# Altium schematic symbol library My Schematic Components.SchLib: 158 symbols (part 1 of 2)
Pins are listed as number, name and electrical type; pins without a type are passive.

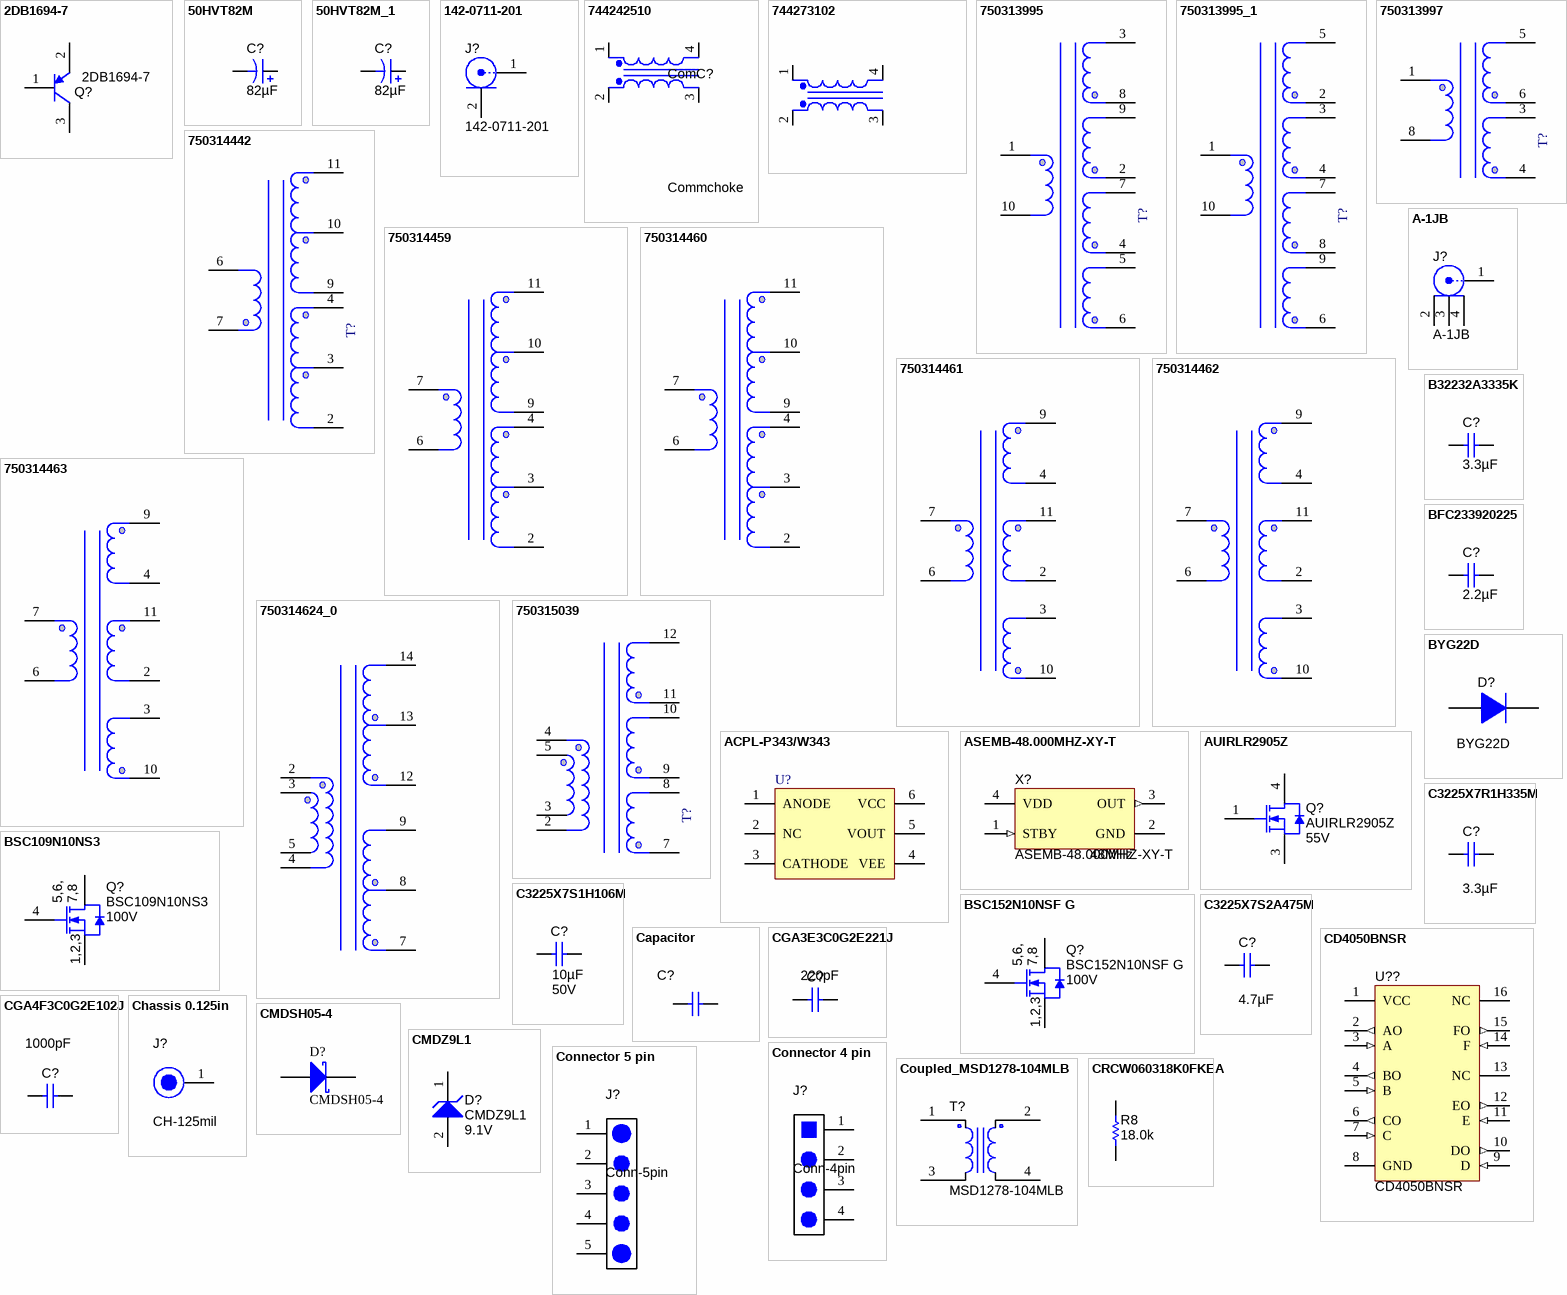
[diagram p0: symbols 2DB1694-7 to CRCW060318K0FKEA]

## 2DB1694-7
designator Q?
TRANS BIPO PNP 30V 1A SOT-323; Manufacturer: Diodes Inc.; CompType: BJT; U/M: EA; PNP: 1; NPN: 0; Vceo_V: 30; Vcesat1_V: 0.380; Value: 0.38V; HfeMax: 680; Value2: 600
simulation model DI_BC858C
footprint SOT-323 DIODES INC
pins: 1 B, 2 E, 3 C

## 50HVT82M
designator C?  ValueDisplayed: 82µF  (hidden comment: 50HVT82M)
CAP, AL EP, 82uF, 50V, +/-20%, 0.019 ohm, SMD; Manufacturer: Suncon; Cap_Case: 10x12.5; ESR_Ohm: 0.019; IRMS_A: 1.27; Polarized: Y; TaMax_C: 135; TaMin_C: -55; Tolerance_%: 20; VDC_V: 50; CompType: Capacitor; Cap_F: 82.0E-6; U/M: EA
signal-integrity model Cap
simulation model Cap
footprint SM_RADIAL_10x12.5mm (Suncon 10x12.5)
pins: 1 +, 2 -

## 50HVT82M_1
designator C?, comment ValueDisplayed: 82µF  (hidden comment: 50HVT82M)
CAP, AL EP, 82uF, 50V, +/-20%, 0.019 ohm, SMD; Manufacturer: Suncon; Cap_Case: 10x12.5; ESR_Ohm: 0.019; IRMS_A: 1.27; Polarized: Y; TaMax_C: 135; TaMin_C: -55; Tolerance_%: 20; VDC_V: 50; CompType: Capacitor; Cap_F: 82.0E-6; U/M: EA
signal-integrity model Cap
simulation model Cap
footprint SM_RADIAL_10x12.5mm (Suncon 10x12.5)
pins: 1 +, 2 -

## 142-0711-201
designator J?
Connector, SMA Jack, Vertical, Gold, SMD; Manufacturer: Emerson Network Power; SymbolCreator: codlsc; U/M: EA
signal-integrity model SI Model (SI Default Model)
footprint 142-0711-201
pins: 1, 2

## 744242510
designator ComC?, comment Commchoke
CHOKE COMM MODE 51uH 2.5kOHM .4A SMD; Manufacturer: Wurth Electronics Inc; PartNumber: 744242510; Filter Type: Data, Signal Line; Number of Lines: 2; ValueDisplayed: 51µH; Irms: 400mA; DCR_Ohm: 320 mOhm Max
footprint WE-SLM Choke (WE-SLM SMD Common Mode Choke)
pins: 1 Sec+, 2 Pri+, 3 Pri-, 4 Sec-

## 744273102
designator L?
Wurth 744273102 2A Common Mode Choke; Manufacturer: Wurth Elektronik; SymbolVersion: use current date i.e. 2008-05-20; SymbolCreator: Use a-id; CompType: Used in some BOM reports.  Useful for finding later.; U/M: EA, IN, or GM
pins: 1 Sec+, 2 Pri+, 3 Pri-, 4 Sec-

## 750313995
designator T?  (value not drawn)
XFMR, SMT 50uH, 3:2:4, 3:2:4; Manufacturer: Wurth; Area: 240 sq. mm
footprint XFMR_Wurth_EP13_10pin_SMT (Recommended land pattern for Pulse Engineering PA3856.006NL transformer)
pins: 1, 2, 3, 4, 5, 6, 7, 8, 9, 10

## 750313995_1
designator T?, comment 750313995  (value not drawn)
XFMR, SMT 50uH, 3:2:4, 3:2:4; Manufacturer: Wurth; Area: 240 sq. mm
footprint XFMR_Wurth_EP13_10pin_SMT (Recommended land pattern for Pulse Engineering PA3856.006NL transformer)
footprint XFMR_Wurth_EP13_EP10_Comb_SMT (Recommended land pattern for Wurth EP13 package (10pin) transformer)
pins: 1, 2, 3, 4, 5, 6, 7, 8, 9, 10

## 750313997
designator T?  (value not drawn)
XFMR, SMT 50uH, 1:1.5:1.5, EP10; Manufacturer: Wurth; Area: 203 sq. mm
footprint XFMR_WURTH_EP10_8PIN_SMT (Recommended land pattern for Wurth EP10 8 pin transformer)
pins: 1, 3, 4, 5, 6, 8

## 750314442
designator T?, comment 750313995  (value not drawn)
XFMR, SMT 50uH, 3:2:4, 3:2:4; Manufacturer: Wurth; Area: 165 sq. mm; Value: 45uH
footprint XFMR_Wurth_ER11p5_12pin_SMT (Recommended land pattern for Wurth ER11p5 - SMT)
pins: 2, 3, 4, 6, 7, 9, 10, 11

## 750314459
designator T?
XFMR, SMT 45uH, 750314459; Manufacturer: Wurth; PCB DECAL: Used in BOM report.  Use Y or N.; Area: 164.465 sq.mm
footprint XFMR_Wurth_ER11p5_12pin_SMT (Recommended land pattern for Wurth ER11p5 - SMT)
pins: 2, 3, 4, 6, 7, 9, 10, 11

## 750314460
designator T?  (value not drawn)
XFMR, SMT 45uH, 750314460; Manufacturer: Wurth; Area: 164.465 sq. mm
footprint XFMR_Wurth_750314460_12pin_SMT (Recommended land pattern for Wurth - SMT)
pins: 2, 3, 4, 6, 7, 9, 10, 11

## 750314461
designator T?
XFMR, SMT 45uH, 750314461; Manufacturer: Wurth Elektronik; PCB DECAL: Used in BOM report.  Use Y or N.; Area: 164.465 sq.mm
footprint Model Name (Footprint not found)
footprint XFMR_Wurth_ER11p5_12pin_SMT (Recommended land pattern for Wurth ER11p5 - SMT)
pins: 2, 3, 4, 6, 7, 9, 10, 11

## 750314462
designator T?
XFMR, SMT 45uH, 750314462; Manufacturer: Wurth Elektronik; PCB DECAL: Used in BOM report.  Use Y or N.; Area: 164.465 sq.mm
footprint XFMR_Wurth_ER11p5_12pin_SMT (Recommended land pattern for Wurth ER11p5 - SMT)
pins: 2, 3, 4, 6, 7, 9, 10, 11

## 750314463
designator T?
XFMR, SMT 45uH, 750314463; Manufacturer: Wurth Elektronik; PCB DECAL: Used in BOM report.  Use Y or N.; Area: 164.465 sq.mm
footprint XFMR_Wurth_ER11p5_12pin_SMT (Recommended land pattern for Wurth ER11p5 - SMT)
pins: 2, 3, 4, 6, 7, 9, 10, 11

## 750314624_0
designator T?
Manufacturer: Wurth
footprint WURTH_750314624_0 (WURTH EF20 through-hole, extended rail)
pins: 2, 3, 4, 5, 7, 8, 9, 12, 13, 14

## 750315039
designator T?  (value not drawn)
Transformer, 45uH, Isat 2.5A, EFD20, 12 pin, SMT, 6:4:11:11; Manufacturer: Wurth Electronics Midcom; Value: 40uH
footprint Wurth_EFD20_12pin_SMT (WURTH EFD20 12pin SMT package)
pins: 2, 3, 4, 5, 7, 8, 9, 10, 11, 12

## A-1JB
designator J?
Connector, RF Jack, Vertical, Gold, SMD; Manufacturer: Amphenol; SymbolCreator: crossc; U/M: EA; Value: 50 ohm
signal-integrity model SI Model (SI Default Model)
footprint A-1JB (Amphenol recommended land pattern)
pins: 1, 2, 3, 4

## ACPL-P343/W343
designator U?
4.0 Amp Output Current IGBT Gate Drive Optocoupler; Manufacturer: Avago Technologies US Inc.; PartNumber: ACPL-W343; Voltage - Isolation: 5000Vrms; Number of Channels: 1, Unidirectional; Current - Output / Channel: 4A; Propagation Delay High - Low @ If: 95ns @ 7mA ~ 16mA; Current - DC Forward (If) (Max): 25mA; Input Type: DC; Output Type: Gate Driver
footprint ACPL-P34x/W34x (AVAGO Stretched SO-6 Package)
pins: 1 ANODE, 2 NC, 3 CATHODE, 4 VEE, 5 VOUT, 6 VCC

## ASEMB-48.000MHZ-XY-T
designator X?  Frequency: 48MHz
Oscillator, 48.000MHz, 1.8-3.3V, SMD; Manufacturer: Abracon Corporation; Function: Standby (Power Down); Output: CMOS; Voltage - Supply: 1.8 V ~ 3.3 V; Frequency Stability: ±10ppm; Current - Supply (Max): 16mA; Current - Supply (Disable) (Max): 15µA
footprint XTAL_ABSEMB3.2_4-SMD (Abracon recommended land pattern)
pins: 1 STBY (in), 2 GND (power), 3 OUT (out), 4 VDD (power)

## AUIRLR2905Z
designator Q?  value 55V
MOSFET, N-CH, 55V, 42A, DPAK; Manufacturer: International Rectifier; Alternate Manufacturer: None; U/M: EA; ChType: N; VdsMax_V: 55; Value1: 0.011 ohm; Rdson: 0.011; Value2: 20 nC; QgTyp_nC: 23; Vgs_V: 16; IdsMax_A: 42
footprint DPAK
pins: 1 G, 3 S, 4 D

## B32232A3335K
designator C?  ValueDisplayed: 3.3µF  (hidden comment: B32232A3335K)
CAP, Film, 3.3uF, 250V, +/-10%, TH; Manufacturer: EPCOS Inc; Polarized: N; TaMax_C: 100; Tolerance_%: 10; VDC_V: 250; Cap_F: 3.3E-6; CompType: Capacitor; Dielectric: B32232; VAC_V: 160; Dielectric Material: Metallized Polyester Film; Maximum Temperature: -40°C ~ 100°C
signal-integrity model Cap
simulation model Cap
footprint CAPPA37-32x14 (Capacitor, Axial; Body 32 x 14 mm (LxDia. max), Lead Dia. 0.8 mm (typ))
pins: 1, 2

## BFC233920225
designator C?, comment ValueDisplayed: 2.2µF  (hidden comment: B32923C3225M)
CAP, Film, 2.2uF, 630V, +/-20%, TH; Manufacturer: EPCOS Inc; Polarized: N; TaMax_C: 110; Tolerance_%: 20; VDC_V: 630; Cap_F: 2.2E-6; CompType: Capacitor; Dielectric: B32923; VAC_V: 310; Dielectric Material: Metallized Polypropylene Film; Lifetime @ Temp.: 1000 Hrs @ 110°C; Maximum Temperature: -55°C ~ 110°C
signal-integrity model Cap
simulation model Cap
footprint MKP_15x25x31.5mm (Flm capacitors, 27.5mm spacing)
pins: 1, 2

## BSC109N10NS3
designator Q?  value 100V
MOSFET, N-CH, 100V, 63A, PG-TDSON-8; Manufacturer: Infineon Technologies; Alternate Manufacturer: None; U/M: EA; ChType: N; VdsMax_V: 100; Value1: 10.9 mohm; Rdson45_Ohm: 0.0125; Value2: 26 nC; QgTyp_nC: 26; Vgs_V: 20; IdsMax_A: 63
footprint PG-TDSON-8
pins: 1 S, 2 S, 3 S, 4 G, 5 D, 6 D, 7 D, 8 D, 9 D

## BSC152N10NSF G
designator Q?  value 100V
MOSFET, N-CH, 100V, 63A, PG-TDSON-8; Manufacturer: Infineon Technologies; Alternate Manufacturer: None; U/M: EA; ChType: N; VdsMax_V: 100; Value1: 101 ohm; Rdson45_Ohm: 101; Value2: 22 nC; QgTyp_nC: 22; Vgs_V: 20; IdsMax_A: 63
footprint PG-TDSON-8
pins: 1 S, 2 S, 3 S, 4 G, 5 D, 6 D, 7 D, 8 D, 9 D

## BYG22D
designator D?
Diode, Ultrafast Avalanche, 200V, 2A, SMA; Manufacturer: Vishay; Vf_V: 1.1; Io_A: 1; Vr_V: 200; TJmax_C: 150; RJC_CperW: 30; Current - Reverse Leakage @ Vr: 1µA @ 200V; Reverse Recovery Time (trr): 25ns; Value: 1.1V
signal-integrity model Diode
footprint SMA - HV (Molded Diode, 2-Leads, Body 4.3x2.6mm. Based on STTH1R06 footprint dimensions and land pattern for 600V.)
pins: 1 K, 2 A

## C3225X7R1H335M
designator C?  ValueDisplayed: 3.3µF  (hidden comment: C3225X7R1H335M)
CAP, CERM, 3.3uF, 50V, +/-20%, X7R, 1210; Manufacturer: TDK; Polarized: N; CompType: Capacitor; U/M: EA; Cap_F: 0.0000033; Tolerance_%: 20; VDC_V: 50; TaMin_C: -55; TaMax_C: 125; Cap_Case: 1210
signal-integrity model Cap
simulation model Cap
footprint 1210
footprint 1210M
footprint 1210L
pins: 1, 2

## C3225X7S1H106M
designator C?  Value2: 50V  ValueDisplayed: 10µF  (hidden comment: C3225X7S1H106M)
CAP, CERM, 10uF, 50V, +/-20%, X7S, 1210; Manufacturer: TDK; Polarized: N; CompType: Capacitor; U/M: EA; Cap_F: 0.000010; Tolerance_%: 20; VDC_V: 50; TaMin_C: -55; TaMax_C: 125; Cap_Case: 1210
signal-integrity model Cap
simulation model Cap
footprint 1210
footprint 1210M
footprint 1210L
pins: 1, 2

## C3225X7S2A475M
designator C?  ValueDisplayed: 4.7µF  (hidden comment: C3225X7S2A475M)
CAP, CERM, 4.7uF, 100V, +/-20%, X7S, 1210; Manufacturer: TDK; Polarized: N; CompType: Capacitor; U/M: EA; Cap_F: 0.0000047; Tolerance_%: 20; VDC_V: 100; TaMin_C: -55; TaMax_C: 125; Cap_Case: 1210
signal-integrity model Cap
simulation model Cap
footprint 1210
footprint 1210M
footprint 1210L
pins: 1, 2

## Capacitor
designator C?, comment Used in BOM report  (value not drawn)
CAP, CERM, xxxF, xxV, [Dielectric], xx%, [Package]; Polarized: N; CompType: Capacitor
simulation model Capacitor
signal-integrity model Cap
footprint TBD (Placeholder for MiscParts)
footprint 0201 (Data from Panasonic ERJ resistor datasheet dated February 2006)
footprint 0402 (0402 from SM-752 data)
footprint 0603 (0603 from SM-752 data)
footprint 0805 (0805 from SM-752 data)
footprint 1206 (1206 from SM-752 data)
footprint 0603_HV (Ernesto recommended land pattern.  26 mil between pads.)
footprint 0805_HV (0805 with 30mil clearance between pads)
footprint 1210 (1210 from SM-752 data)
footprint 1808 (Chip Capacitor, Body 4.6x2.0mm, IPC Medium Density)
footprint 1812
footprint 1825 (Chip Capacitor, Body 4.5x6.4mm, IPC Medium Density)
footprint 2220 (Chip Capacitor, Body 5.7x5.0mm, IPC Medium Density)
footprint 2225 (Chip Capacitor, Body 5.7x6.4mm, IPC Medium Density)
pins: 1, 2
1 alternate drawing of the same symbol

## CD4050BNSR
designator U??
IC BUFF/CONVERTER HEX 16SOP; Manufacturer: Texas Instruments; Voltage - Supply: 3 V ~ 18 V
footprint NS016_N (16-Pin Small Outline Package 1.27 mm Pitch, IPC Medium Density)
footprint NS016_L (16-Pin Small Outline Package 1.27 mm Pitch, IPC High Density)
footprint NS016_M (16-Pin Small Outline Package 1.27 mm Pitch, IPC Low Density)
3D model NS016 (PCB3D Model)
pins: 1 VCC (power), 2 AO (out), 3 A (in), 4 BO (out), 5 B (in), 6 CO (out), 7 C (in), 8 GND (power), 9 D (in), 10 DO (out), 11 E (in), 12 EO (out), 13 NC, 14 F (in), 15 FO (out), 16 NC

## CGA3E3C0G2E221J
designator C?, comment value 220pF  (hidden comment: CGA3E3C0G2E221J080AA)
CAP, CERM, 4.7uF, 100V, +/-20%, X7S, 1210; Manufacturer: TDK Corporation; Description: CAP CER 220PF 250V 5% C0G 0603; Tolerance_%: ±5%; VDC_V: 250V; TempCo: C0G, NP0
footprint 0603 (0603 from SM-752 data)
pins: 1, 2

## CGA4F3C0G2E102J
designator C?, comment value 1000pF  (hidden comment: CGA4F3C0G2E102J085AA)
CAP, CERM, 4.7uF, 100V, +/-20%, X7S, 1210; Manufacturer: TDK Corporation; Description: CAP CER 1000PF 250V 5% C0G 0805; Tolerance_%: ±5%; VDC_V: 250V; TempCo: C0G, NP0
footprint 0805 (0805 from SM-752 data)
pins: 1, 2

## Chassis 0.125in
designator J?, comment CH-125mil
Chassis 0.125in; SymbolCreator: crossc; CompType: Connector; U/M: EA
signal-integrity model SI Model (SI Default Model)
footprint Chassis 0.125in
pins: 1

## CMDSH05-4
designator D?
Vr = 40V, Io = 0.5A, Vf = 0.47V; Manufacturer: Central Semiconductor; Vf_V: 0.47; Io_A: 0.5; Vr_V: 40; TJMax_C: 125; Type: Schottky; CompType: Diode
signal-integrity model Diode
simulation model DI_BAT54WS
footprint sod-323 (Diodes Inc recommended land pattern)
pins: 1 K, 2 A

## CMDZ9L1
designator D?  value 9.1V
Diode, Zener, 9.1V, 250mW, SOD-323; Manufacturer: Central Semiconductor; U/M: EA; Power_W: 0.25; Vz_V: 9.1; Value1: 0.25W; RJA_CperW: 500
signal-integrity model Diode
footprint sod-323
pins: 1 K, 2 A

## Connector 4 pin
designator J?, comment Conn-4pin
Connector 4 pin; SymbolCreator: crossc; U/M: EA
signal-integrity model SI Model (SI Default Model)
footprint Connector 4 pin
pins: 1, 2, 3, 4

## Connector 5 pin
designator J?, comment Conn-5pin
Connector 5 pin; SymbolCreator: crossc; U/M: EA
signal-integrity model SI Model (SI Default Model)
footprint Connector 5 pin
pins: 1, 2, 3, 4, 5

## Coupled_MSD1278-104MLB
designator T?, comment MSD1278-104MLB
Coupled inductor, 100uH, 3.4A, 0.3 ohm, +/-20%, SMD; Manufacturer: Coilcraft; U/M: EA; ComponentName: Coupled_MSD1260-104MLB; Ind_H: 0.0001; DCR_Ohm: 0.3; Isat: 3.4; Tolerance_%: 20
footprint MSD1278-COUPLED
pins: 1, 2, 3, 4

## CRCW060318K0FKEA
designator R8  value 18.0k  (hidden comment: CRCW060318K0FKEA)
RES, 18.0k ohm, 1%, 0.1W, 0603; Manufacturer: Vishay-Dale; CompType: Resistor; Res_ohm: 7500; Value_Code: 18k0; Tolerance_%: 1; Power_W: 0.1; VDC_V: 75; TempCo: 100 ppm/C; EIA_Code: E96; U/M: EA
signal-integrity model Resistor
simulation model Resistor
footprint 0603
footprint 0603M
footprint 0603L
footprint 0603_HV
pins: 1, 2

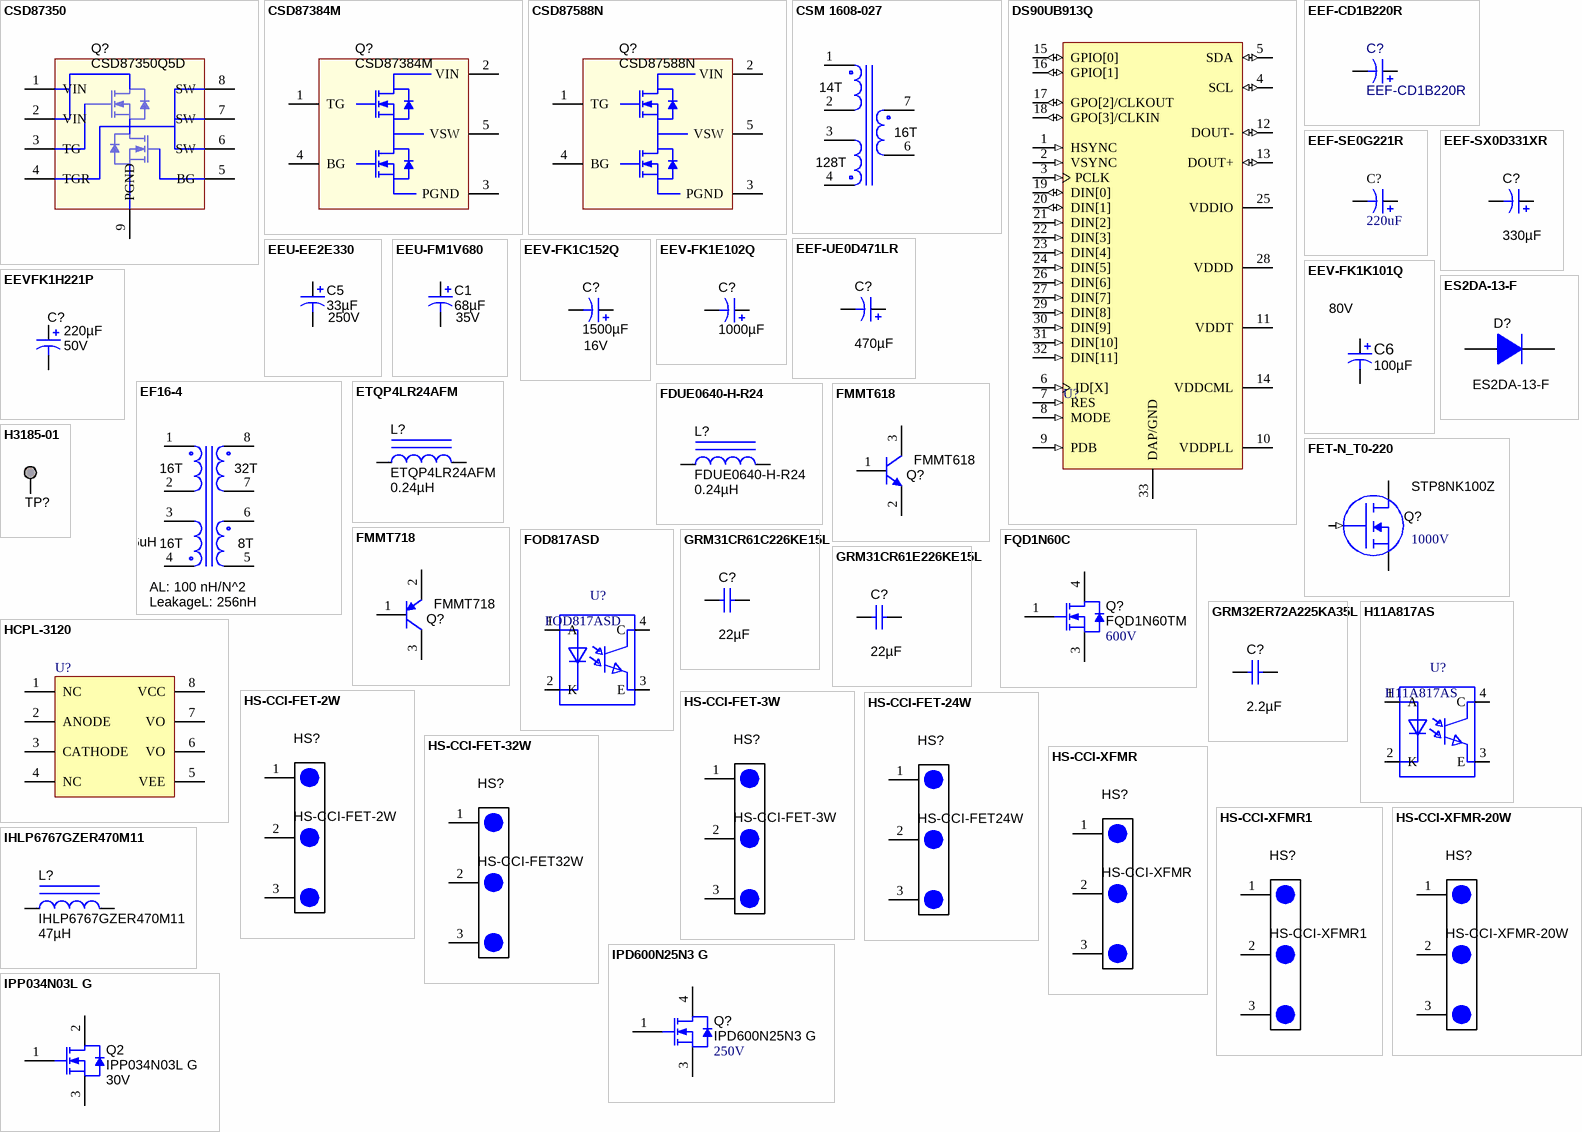
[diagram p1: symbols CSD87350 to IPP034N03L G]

## CSD87350
designator Q?, comment CSD87350Q5D
NexFET Power Block, 30V, 40A, SON 5mm x 6mm; Manufacturer: Texas Instruments; CompType: MOSFET; ChType: N; VdsMax_V: 30; Value1: 0.005 ohm; Value2: 20 nC; QgTyp_nC: 20; Vgs_V: 8; IdsMax_A: 40
footprint TRANS_NexFET_Q5D (TI recommended land pattern (nominal) M0188-01)
pins: 1 VIN, 2 VIN, 3 TG, 4 TGR, 5 BG, 6 SW, 7 SW, 8 SW, 9 PGND

## CSD87384M
designator Q?
NexFET Power Block II, 30V, 40A, 5mm x 3.5mm; Manufacturer: Texas Instruments; CompType: MOSFET; ChType: N; VdsMax_V: 30; Value1: 0.002 ohm; Value2: 5.4 nC; QgTyp_nC: 5.4; Vgs_V: 8; IdsMax_A: 40
footprint CSD87384M (TI recommended land pattern SLPS-JUNE 2012)
pins: 1 TG, 2 VIN, 3 PGND, 4 BG, 5 VSW

## CSD87588N
designator Q?
NexFET Power Block II, 30V, 35A, 5mm x 2.5mm; Manufacturer: Texas Instruments; CompType: MOSFET; ChType: N; VdsMax_V: 30; Value1: 0.003 ohm; Value2: 4.2 nC; QgTyp_nC: 4.2; Vgs_V: 8; IdsMax_A: 35
footprint CSD87588N (TI recommended land pattern SLPS-JUNE 2012)
pins: 1 TG, 2 VIN, 3 PGND, 4 BG, 5 VSW

## CSM 1608-027
designator T?
Cramer Coil Offline Flyback Transformer; SymbolCreator: crossc; LeakageL: ?uH; Lp: 1.65mH; Core: C40 EE16
footprint CSM 1608 (Cramer Coil Offline Flyback Transformer)
pins: 1, 2, 3, 4, 6, 7

## DS90UB913Q
designator U?
10 - 43MHz 14 Bit Color FPD-Link III Serializer with Bi-Directional Control Channel, 32 pin LLP; PartNumber: DS90UB913Q; Manufacturer: Texas Instruments; PowerWise: N; CompType: Interface IC
footprint SQA32A (QFN, 32-Leads, Body 5x5mm, Pitch 0.5mm, NSC Recommended)
pins: 1 HSYNC (in), 2 VSYNC (in), 3 PCLK (in), 4 SCL (io), 5 SDA (io), 6 ID[X] (in), 7 RES (in), 8 MODE (in), 9 PDB (in), 10 VDDPLL (power), 11 VDDT (power), 12 DOUT- (io), 13 DOUT+ (io), 14 VDDCML (power), 15 GPIO[0] (io), 16 GPIO[1] (io), 17 GPO[2]/CLKOUT  (io), 18 GPO[3]/CLKIN (io), 19 DIN[0] (io), 20 DIN[1] (io), 21 DIN[2] (in), 22 DIN[3] (in), 23 DIN[4] (in), 24 DIN[5] (in), 25 VDDIO (power), 26 DIN[6] (in), 27 DIN[7] (in), 28 VDDD (power), 29 DIN[8] (in), 30 DIN[9] (in), 31 DIN[10] (in), 32 DIN[11] (in), 33 DAP/GND (power)

## EEF-CD1B220R
designator C?
CAP ALUM 22UF 12.5V 20% SMD; Manufacturer: Panasonic-ECG; CompType: Used in BOM report; SymbolVersion: 2012 - 04 - 16; SymbolCreator: cdnlsc
footprint Model Name (Footprint not found)
footprint EEFLX0D471R4
pins: 1 +, 2 -, 3 -

## EEF-SE0G221R
designator C?  value 220uF  (hidden comment: EEF-SE0G221R)
SP, 4V, 20%, 0.005 Ohm ESR; Manufacturer: Panasonic; Cap_Case: D; ESR_Ohm: 0.005; IRMS_A: 3.7; Polarized: Y; TaMax_C: 105; TaMin_C: -40; Tolerance_%: 20; VDC_V: 4; CompType: Capacitor; Cap_F: 220.0E-6; Value1: 0.007 Ohm; Dielectric: UE
signal-integrity model Cap
simulation model Cap
footprint CAPSMT_6_UE (Recommended land pattern for Panaosonic UE series of SP-CAP capacitors)
pins: 1 +, 2 -

## EEF-SX0D331XR
designator C?  ValueDisplayed: 330µF  (hidden comment: EEF-SX0D331XR)
CAP, AL, 330uF, 2V, +/-20%, 0.006 ohm, SMD; Manufacturer: Panasonic; Polarized: Y; CompType: Capacitor; U/M: EA; Cap_F: 0.00033; Tolerance_%: 20; VDC_V: 2; ESR_Ohm: 0.006; IRMS_A: 3.5; TaMin_C: -40; TaMax_C: 105; Cap_Case: D
signal-integrity model Cap
simulation model Cap
footprint CAPSMT_6_UE
pins: 1 +, 2 -

## EEF-UE0D471LR
designator C?  ValueDisplayed: 470µF  (hidden comment: EEF-UE0D471LR)
CAP, AL, 470uF, 2V, +/-20%, 0.007 ohm, SMD; Manufacturer: Panasonic; Polarized: Y; CompType: Capacitor; U/M: EA; Cap_F: 0.00047; Tolerance_%: 20; VDC_V: 2; ESR_Ohm: 0.007; IRMS_A: 3.7; TaMin_C: -40; TaMax_C: 105; Cap_Case: D
signal-integrity model Cap
simulation model Cap
footprint CAPSMT_6_UE
pins: 1 +, 2 -

## EEU-EE2E330
designator C5  ValueDisplayed: 33µF  Value2: 250V  (hidden comment: EEU-EE2E330)
CAP, AL, 33uF, 250V, +/-20%, TH; Manufacturer: Panasonic; IRMS_A: 0.995; Polarized: Y; TaMax_C: 105; TaMin_C: -25; Tolerance_%: 20; VDC_V: 250; CompType: Capacitor; Cap_F: 33.0E-6; U/M: EA; Dielectric: EE
signal-integrity model Cap
simulation model Cap
footprint CAPPR5-12.5X20 (Capacitor, Electrolytic, Radial; Body 12.5 x 20 mm (Dia.xH typ); Pin Spacing 5 mm (typ))
pins: 1 +, 2 -

## EEU-FM1V680
designator C1  ValueDisplayed: 68µF  Value2: 35V  (hidden comment: EEU-FM1V680)
CAP, AL, 68uF, 35V, +/-20%, 0.13 ohm, TH; Manufacturer: Panasonic; Cap_Case: 6.3x11.2; ESR_Ohm: 0.13; IRMS_A: 0.455; Polarized: Y; TaMax_C: 105; TaMin_C: -55; Tolerance_%: 20; VDC_V: 35; CompType: Capacitor; Cap_F: 68.0E-6; U/M: EA; Dielectric: FM
signal-integrity model Cap
simulation model Cap
footprint CAPPR2.5-6.3X11 (Capacitor, Electrolytic, Radial; Body 6.3 x 11 mm (Dia.xH typ); Pin Spacing 2.5 mm (typ))
pins: 1 +, 2 -

## EEV-FK1C152Q
designator C?  Value2: 16V  ValueDisplayed: 1500µF  (hidden comment: EEV-FK1C152Q)
CAP, AL, 1500uF, 16V, +/-20%, 0.06 ohm, SMD; Manufacturer: Panasonic; Polarized: Y; CompType: Capacitor; U/M: EA; Cap_F: 0.0015; Tolerance_%: 20; VDC_V: 16; ESR_Ohm: 0.06; IRMS_A: 1.1; TaMin_C: -55; TaMax_C: 105; Cap_Case: H13
signal-integrity model Cap
simulation model Cap
footprint SM_RADIAL_H13 (Footprint not found)
pins: 1 +, 2 -

## EEV-FK1E102Q
designator C?  ValueDisplayed: 1000µF  (hidden comment: EEV-FK1E102Q)
CAP, AL, 1000uF, 25V, +/-20%, 0.06 ohm, SMD; Manufacturer: Panasonic; Polarized: Y; CompType: Capacitor; U/M: EA; Cap_F: 0.001; Tolerance_%: 20; VDC_V: 25; ESR_Ohm: 0.06; IRMS_A: 1.1; TaMin_C: -55; TaMax_C: 105; Cap_Case: H13
signal-integrity model Cap
simulation model Cap
footprint SM_RADIAL_H13 (12.5 x 13.5mm:  Panasonic H13)
pins: 1 +, 2 -

## EEV-FK1K101Q
designator C6  Value2: 80V  ValueDisplayed: 100µF  (hidden comment: EEV-FK1K101Q)
CAP, AL, 100uF, 80V, +/-20%, 0.32 ohm, SMD; Manufacturer: Panasonic; Cap_Case: H13; ESR_Ohm: 0.32; IRMS_A: 0.5; Polarized: Y; TaMax_C: 105; TaMin_C: -55; Tolerance_%: 20; VDC_V: 80; CompType: Capacitor; Cap_F: 0.0001; U/M: EA
signal-integrity model Cap
simulation model Cap
footprint SM_RADIAL_H13
pins: 1 +, 2 -

## EEVFK1H221P
designator C?  Value2: 50V  ValueDisplayed: 220µF  (hidden comment: EEVFK1H221P)
CAP, AL, 220uF, 50V, +/-20%, 0.1 ohm, SMD; Manufacturer: Panasonic; Polarized: N; CompType: Capacitor; Value: 220µF; U/M: EA; Cap_F: 0.00000000022; Tolerance_%: 20; Value1: 0.1 ohm; VDC_V: 50; ESR_Ohm: 0.1; TaMin_C: -55; TaMax_C: 125; Cap_Case: G
signal-integrity model Cap
simulation model Cap
footprint SM_RADIAL_G
pins: 1 +, 2 -

## EF16-4
designator T?, comment EF16  LeakageL: 256nH  Lp: 25.6uH  AL: 100 nH/N^2
EF16 Flyback Transformer; Manufacturer: TBD; SymbolCreator: crossc; Core: C40 EE16
footprint CSM 1608 (Cramer Coil Offline Flyback Transformer)
pins: 1, 2, 3, 4, 5, 6, 7, 8

## ES2DA-13-F
designator D?
Diode, Ultrafast, 200V, 2A, SMA; Manufacturer: Diodes Inc.; Vf_V: 1.0; Io_A: 1; Vr_V: 200; TJmax_C: 175; RJC_CperW: 30; Current - Reverse Leakage @ Vr: 5µA @ 200V; Speed: Fast Recovery =< 500ns, > 200mA (Io); Reverse Recovery Time (trr): 25ns; Value: 1.0V
signal-integrity model Diode
footprint SMA - HV (Molded Diode, 2-Leads, Body 4.3x2.6mm. Based on STTH1R06 footprint dimensions and land pattern for 600V.)
pins: 1 K, 2 A

## ETQP4LR24AFM
designator L?  ValueDisplayed: 0.24µH
Inductor, Shielded Composite Powder, 0.24uH, 24A, 0.001 ohm, SMD; Manufacturer: Panasonic; Ind_H: 0.24E-6; Imax_A: 24; Irms: 24A @ 40C rise; Isat: 24A @ 20% inductance drop; DCR_ohm: 0.001; Material: Powdered Iron; U/M: EA
signal-integrity model Inductor
simulation model Inductor
footprint Inductor-7mm-to-10mm-square (Custom land pattern)
pins: 1, 2

## FDUE0640-H-R24
designator L?  ValueDisplayed: 0.24µH
Inductor, Shielded Iron Powder, 0.24uH, 27A, 0.00089 ohm, SMD; Manufacturer: Toko; Ind_H: 0.24E-6; Imax_A: 27; Irms: 27A @ 40C rise; Isat: 19A @ 20% inductance drop; Material: Powdered Iron; U/M: EA
signal-integrity model Inductor
simulation model Inductor
footprint Inductor-7mm-to-10mm-square (Custom land pattern)
pins: 1, 2

## FET-N_T0-220
designator Q?, comment STP8NK100Z  Vds: 1000V
MOSFET; Manufature Part number: STP3N150; Manufacture: ST Microelectronics; RDS on: 6ohms; A: 2.5A
footprint TO220-3_A
pins: 1 G (in), 2 D, 3 S

## FMMT618
designator Q?
Transistor, NPN, 20V, 1.5A, SOT-23; Manufacturer: Diodes Inc.; CompType: BJT; PNP: 1; NPN: 0; Vceo_V: 20; Vcesat1_V: 0.25; Value: 0.22V; IcRated_A: 0.2; HfeMax: 400; Vce Saturation (Max) @ Ib, Ic: 220mV @ 50mA, 1.5A; Current - Collector Cutoff (Max): 100nA; DC Current Gain (hFE) (Min) @ Ic, Vce: 300 @ 100mA, 2V; Power - Max: 625mW; Frequency - Transition: 180MHz
footprint SOT-23
footprint SOT-23M
footprint SOT-23L
pins: 1 B, 2 E, 3 C

## FMMT718
designator Q?
Transistor, PNP, 20V, 1.5A, SOT-23; Manufacturer: Diodes Inc.; CompType: BJT; PNP: 1; NPN: 0; Vceo_V: 20; Vcesat1_V: 0.25; Value: 0.22V; IcRated_A: 0.2; HfeMax: 400; Vce Saturation (Max) @ Ib, Ic: 220mV @ 50mA, 1.5A; Current - Collector Cutoff (Max): 100nA; DC Current Gain (hFE) (Min) @ Ic, Vce: 300 @ 100mA, 2V; Power - Max: 625mW; Frequency - Transition: 180MHz
footprint SOT-23
footprint SOT-23M
footprint SOT-23L
pins: 1 B, 2 E, 3 C

## FOD817ASD
designator U?
IC, Optocoupler, 5000V, 80-160% CTR; Manufacturer: Fairchild Optoelectronics Group; Value: FODA817ASD; Area: 93500; PCB DECAL: SMT_4PDIP
footprint FOD817AS (FOD817AS recommended footprint)
pins: 1 A, 2 K, 3 E, 4 C

## FQD1N60C
designator Q?, comment FQD1N60TM  value 600V
MOSFET, N-CH, 600V, 1A, DPAK; Manufacturer: Fairchild Semiconductor; ChType: N; VdsMax_V: 600; Value1: 11.5 ohm; Value2: 4.8 nC; QgTyp_nC: 4.8; Vgs_V: 30; IdsMax_A: 1
footprint DPAK
pins: 1 G, 3 S, 4 D

## GRM31CR61C226KE15L
designator C?  ValueDisplayed: 22µF  (hidden comment: GRM31CR61C226KE15L)
CAP, CERM, 22uF, 16V, +/-10%, X5R, 1206; Manufacturer: MuRata; Polarized: N; CompType: Capacitor; U/M: EA; Cap_F: 0.000022; Tolerance_%: 10; VDC_V: 16; TaMin_C: -55; TaMax_C: 85; Cap_Case: 1206
signal-integrity model Cap
simulation model Cap
footprint 1206
footprint 1206M
footprint 1206L
pins: 1, 2

## GRM31CR61E226KE15L
designator C?  ValueDisplayed: 22µF  (hidden comment: GRM31CR61E226KE15L)
CAP, CERM, 22uF, 25V, +/-10%, X5R, 1206; Manufacturer: MuRata; Polarized: N; CompType: Capacitor; U/M: EA; Cap_F: 0.000022; Tolerance_%: 10; VDC_V: 25; TaMin_C: -55; TaMax_C: 85; Cap_Case: 1206
signal-integrity model Cap
simulation model Cap
footprint 1206
footprint 1206M
footprint 1206L
pins: 1, 2

## GRM32ER72A225KA35L
designator C?  ValueDisplayed: 2.2µF  (hidden comment: GRM32ER72A225KA35L)
CAP, CERM, 2.2uF, 100V, +/-10%, X7R, 1210; Manufacturer: MuRata; Polarized: N; CompType: Capacitor; U/M: EA; Cap_F: 0.0000022; Tolerance_%: 10; ESR_Ohm: 0.007; Value1: 0.007 ohm; VDC_V: 100; IRMS_A: 4.4; TaMin_C: -55; TaMax_C: 125; Cap_Case: 1210
signal-integrity model Cap
simulation model Cap
footprint 1210
footprint 1210M
footprint 1210L
pins: 1, 2

## H11A817AS
designator U?
IC, Optocoupler, 5300-V, 80-160% CTR; Manufacturer: QT Optoelectronics; Area: 93500; PCB DECAL: SMT_4PDIP
pins: 1 A, 2 K, 3 E, 4 C

## H3185-01
designator TP?  (value not drawn)
Socket, 1mm Single pin; Manufacturer: Harwin; U/M: EA
footprint SOCKET_H3185-01
pins: 1

## HCPL-3120
designator U?
2.0 Amp Output Current IGBT Gate Drive Optocoupler; Manufacturer: Avago Technologies US Inc.; PartNumber: HCPL-3120-300E; Voltage - Isolation: 3750Vrms; Number of Channels: 1, Unidirectional; Current - Output / Channel: 2.5A; Propagation Delay High - Low @ If: 300ns @ 7mA ~ 16mA; Current - DC Forward (If): 25mA; Input Type: DC; Output Type: Gate Driver
footprint ACPL-4800 (AVAGO)
pins: 1 NC, 2 ANODE, 3 CATHODE, 4 NC, 5 VEE, 6 VO, 7 VO, 8 VCC

## HS-CCI-FET-2W
designator HS?
MOSFET Heat Sink 3.5in x 0.8in; SymbolCreator: crossc; U/M: EA
signal-integrity model SI Model (SI Default Model)
footprint HS-CCI-FET (CCI MOSFET heat sink)
pins: 1, 2, 3

## HS-CCI-FET-3W
designator HS?
MOSFET Heat Sink 3.5in x 0.8in; SymbolCreator: crossc; U/M: EA
signal-integrity model SI Model (SI Default Model)
footprint HS-CCI-FET (CCI MOSFET heat sink)
pins: 1, 2, 3

## HS-CCI-FET-24W
designator HS?, comment HS-CCI-FET24W
MOSFET Heat Sink 24W 3.5in x1in; Manufacturer: CCI; PartNumber: mosfet-3w-hsink 00Z91170101; SymbolCreator: crossc; U/M: EA
signal-integrity model SI Model (SI Default Model)
footprint HS-CCI-FET-24W (CCI MOSFET 24W heat sink)
pins: 1, 2, 3

## HS-CCI-FET-32W
designator HS?, comment HS-CCI-FET32W
MOSFET Heat Sink 32W 3.3in x1.1in; Manufacturer: CCI; PartNumber: mosfet-2w-hsink 00Z91160101; SymbolCreator: crossc; U/M: EA
signal-integrity model SI Model (SI Default Model)
footprint HS-CCI-FET-32W (CCI MOSFET 32W heat sink)
pins: 1, 2, 3

## HS-CCI-XFMR
designator HS?
Transformer Heat Sink 3.5in x 1.5in; SymbolCreator: crossc; U/M: EA
signal-integrity model SI Model (SI Default Model)
footprint HS-CCI-XFMR (CCI transformer heat sink)
pins: 1, 2, 3

## HS-CCI-XFMR1
designator HS?
Heat Sink 3.5in x 2in; SymbolCreator: crossc; U/M: EA
signal-integrity model SI Model (SI Default Model)
footprint HS-CCI-XFMR1 (CCI transformer heat sink)
pins: 1, 2, 3

## HS-CCI-XFMR-20W
designator HS?
Transformer Heat Sink 20W 3.5in x 1.5in; Manufacturer: CCI; PartNumber: transformer-hsink 00Z91150101; SymbolCreator: crossc; U/M: EA
signal-integrity model SI Model (SI Default Model)
footprint HS-CCI-XFMR-20W (CCI Transformer 20W heat sink)
pins: 1, 2, 3

## IHLP6767GZER470M11
designator L?  ValueDisplayed: 47µH
Inductor, Shielded Composite Powder, 47uH, 8.6A, 0.0407 ohm, SMD; Manufacturer: Vishay-Dale; Ind_H: 47.0E-6; Imax_A: 8.6; Irms: 8.7A @ 40C rise; Isat: 8.6A @ 20% inductance drop; DCR_ohm: 0.0407; Material: Powdered Iron; U/M: EA
signal-integrity model Inductor
simulation model Inductor
footprint IHLP-6767GZ-11 (Vishay Dale land pattern with wider pad.  Document 34282 rev 30-Aug-10)
pins: 1, 2

## IPD600N25N3 G
designator Q?  value 250V
MOSFET, N-CH, 250V, 25A, DPAK; Manufacturer: Infineon Technologies; ChType: N; VdsMax_V: 250; Value1: 0.06 ohm; Value2: 22 nC; QgTyp_nC: 22; Vgs_V: 20; IdsMax_A: 25
footprint DPAK
pins: 1 G, 3 S, 4 D

## IPP034N03L G
designator Q2  value 30V
MOSFET, N-CH, 30V, 80A, TO-220; Manufacturer: Infineon Technologies; Alternate Manufacturer: None; U/M: EA; ChType: N; VdsMax_V: 30; Value1: 0.0034 ohm; Rdson45_Ohm: 0.0038; Value2: 25 nC; QgTyp_nC: 25; Vgs_V: 20; IdsMax_A: 120
footprint TO-220AB (Footprint not found)
pins: 1 G, 2 D, 3 S

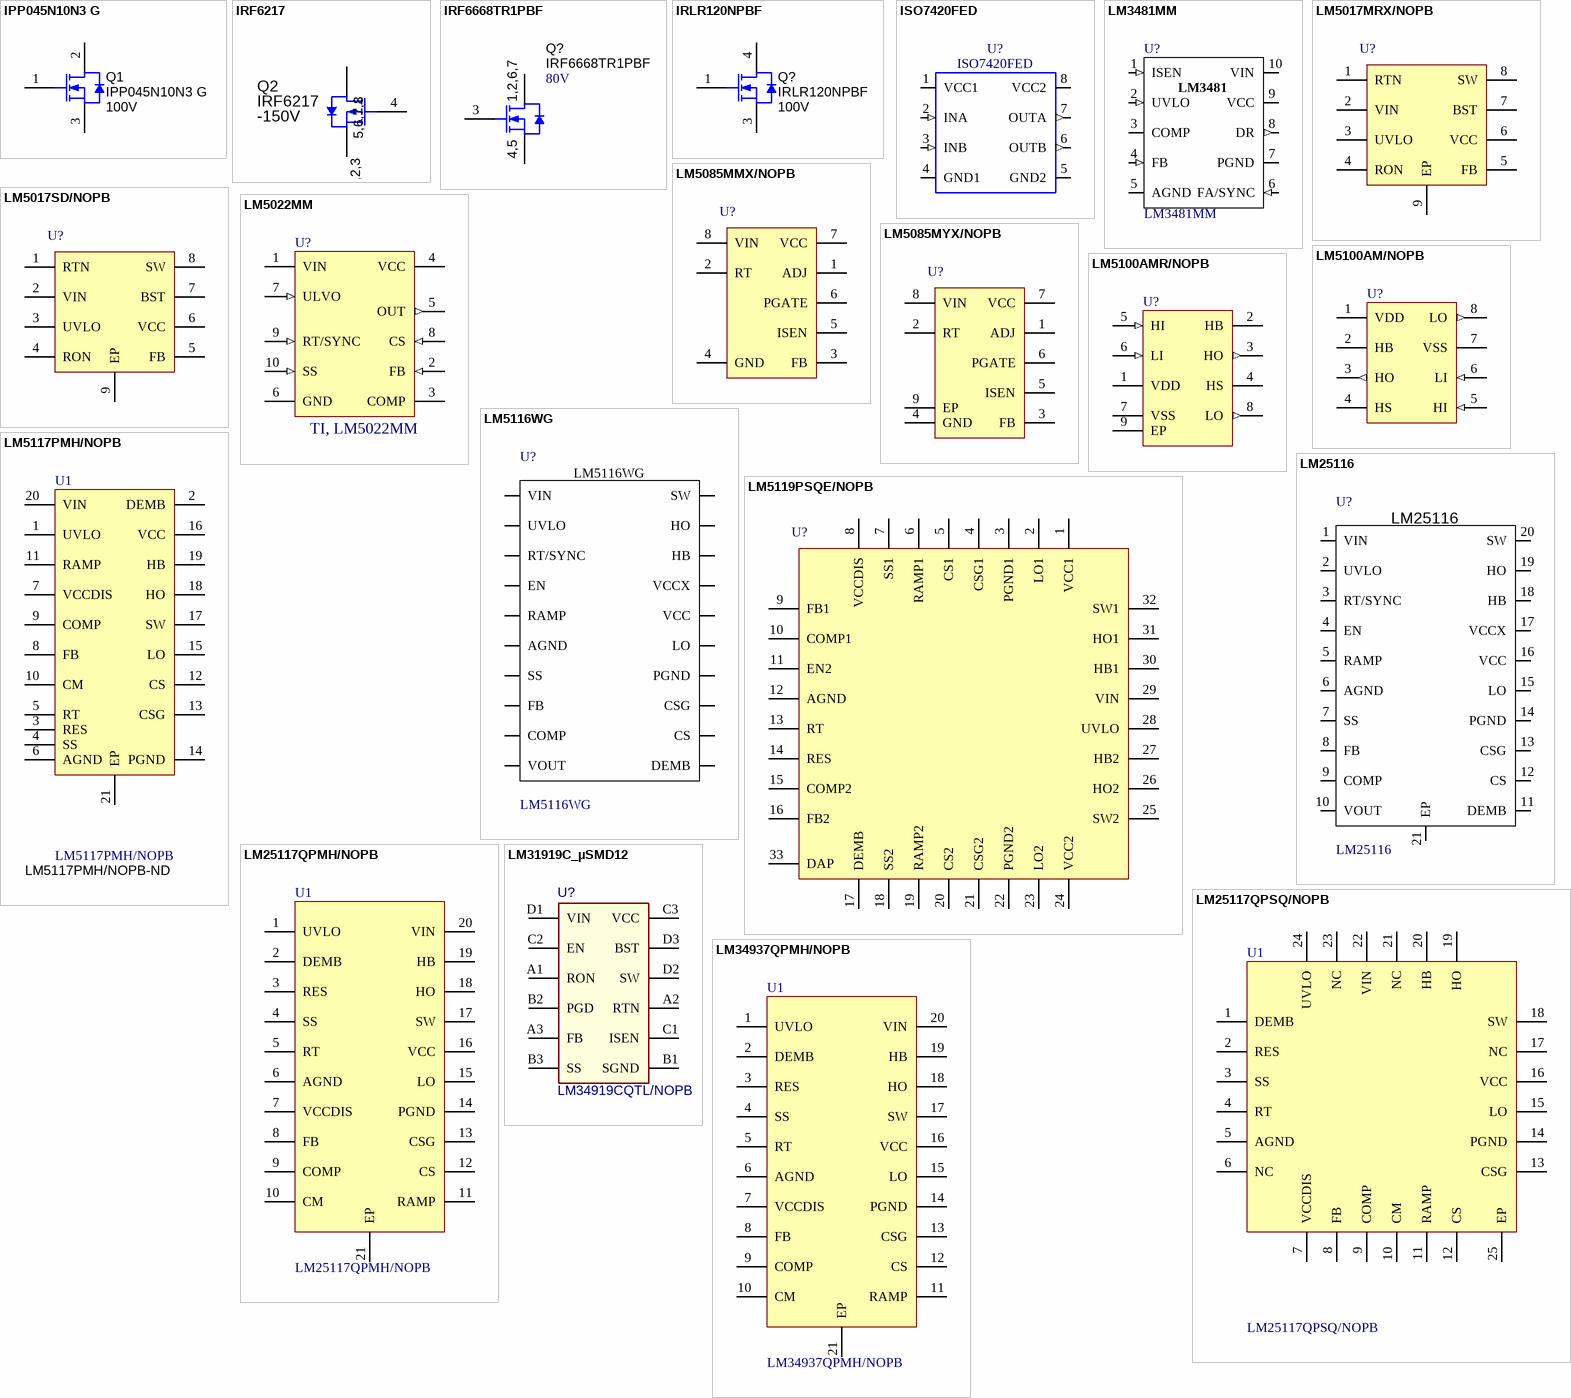
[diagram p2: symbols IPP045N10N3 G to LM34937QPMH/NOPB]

## IPP045N10N3 G
designator Q1  value 100V
MOSFET, N-CH, 100V, 100A, TO-220; Manufacturer: Infineon Technologies; Alternate Manufacturer: None; U/M: EA; ChType: N; VdsMax_V: 100; Value1: 0.0042 ohm; Rdson45_Ohm: 0.0042; Value2: 88 nC; QgTyp_nC: 155; Vgs_V: 20; IdsMax_A: 120
footprint TO-220AB (Footprint not found)
pins: 1 G, 2 D, 3 S

## IRF6217
designator Q2  value -150V
MOSFET, P-CH, -150V, -0.7A, SO-8; Manufacturer: Vishay-Siliconix; PartNumber: IRF6217TRPBF; ChType: P; VdsMax_V: -150; Value1: 2.4 ohm; Rdson_Ohm: 2.4; Value2: 6 nC; QgTyp_nC: 6; Vgs_V: -20; IdsMax_A: -0.7
footprint SOIC-8
footprint SOIC-8M
footprint SOIC-8L
pins: 1 S, 2 S, 3 S, 4 G, 5 D, 6 D, 7 D, 8 D

## IRF6668TR1PBF
designator Q?  value 80V
MOSFET, N-CH, 80V, 55A, DirectFET MZ; Manufacturer: International Rectifier; ChType: N; VdsMax_V: 80; Value2: 22 nC; QgTyp_nC: 22; Vgs_V: 20; IdsMax_A: 55
footprint DirectFET MZ (International Rectifier DirectFET MZ footprint)
pins: 1 D, 2 D, 3 G, 4 S, 5 S, 6 D, 7 D

## IRLR120NPBF
designator Q?  value 100V
MOSFET, N-CH, 100V, 10A, DPAK; Manufacturer: International Rectifier; Alternate Manufacturer: None; U/M: EA; ChType: N; VdsMax_V: 100; Value1: 0.245 ohm; Rdson45_Ohm: 0.245; Value2: 20 nC; QgTyp_nC: 20; Vgs_V: 16; IdsMax_A: 10
footprint DPAK
simulation model irlru120n
pins: 1 G, 3 S, 4 D

## ISO7420FED
designator U?
IC, DUAL DIGITAL ISOLATORS; Manufacturer: Texas Instruments; Second Source: C:\program files\p-cad 2004\pcad_pdf's\iso7220a.pdf; Reference: \\vette02\pmp_pcb\pcad_pdf's\iso7220a.pdf; Area: 69000; Value: ISO72420FED; PCB DECAL: SO8-HV
footprint D008_L (8-Pin Small Outline Integrated Circuit 1.27 mm Pitch, IPC High Density)
footprint D008_M (8-Pin Small Outline Integrated Circuit 1.27 mm Pitch, IPC Low Density)
footprint D008_N (8-Pin Small Outline Integrated Circuit 1.27 mm Pitch, IPC Medium Density)
pins: 1 VCC1 (power), 2 INA (in), 3 INB (in), 4 GND1 (power), 5 GND2 (power), 6 OUTB (out), 7 OUTA (out), 8 VCC2 (power)

## LM3481MM
designator U?
Low-Side N-Channel Controller; CompType: Switcher; Vendor: National Semiconductor; base_pn: LM3481
footprint MUB10A
footprint MUB10AM
footprint MUB10AL
pins: 1 ISEN (in), 2 UVLO (in), 3 COMP (io), 4 FB (in), 5 AGND (power), 6 FA/SYNC (in), 7 PGND (power), 8 DR (out), 9 VCC (power), 10 VIN (power)

## LM5017MRX/NOPB
designator U?
100V Constant On-Time PFET Buck Switching Controller, 8-pin PSOP, Pb-Free; PartNumber: LM5017MRX/NOPB; Manufacturer: National Semiconductor; PowerWise: Y; CompType: Switcher
footprint MRA08A_L (SOIC, 8-Leads, Body 4.9x3.9mm, Pitch 1.27mm, Exposed Pad, IPC High Density)
footprint MRA08A_M (SOIC, 8-Leads, Body 4.9x3.9mm, Pitch 1.27mm, Exposed Pad, IPC Low Density)
footprint MRA08A_N (SOIC, 8-Leads, Body 4.9x3.9mm, Pitch 1.27mm, Exposed Pad, IPC Medium Density)
footprint MRA08A_NS (SOIC, 8-Leads, Body 193x154mil, Pitch 50mil, Exposed Pad, NS Recommended Footprint)
pins: 1 RTN, 2 VIN, 3 UVLO, 4 RON (power), 5 FB, 6 VCC, 7 BST (power), 8 SW, 9 EP

## LM5017SD/NOPB
designator U?
100V Constant On-Time PFET Buck Switching Controller, 8-pin LLP, Pb-Free; PartNumber: LM5017SD/NOPB; Manufacturer: National Semiconductor; PowerWise: Y; CompType: Switcher
footprint SDC08B (SON, 8-Leads, Body 4x4mm, Pitch 0.8mm, NSC Recommended)
pins: 1 RTN, 2 VIN, 3 UVLO, 4 RON (power), 5 FB, 6 VCC, 7 BST (power), 8 SW, 9 EP

## LM5022MM
designator U?, comment TI, LM5022MM
60V Low Side  Controller for Boost and SEPIC; Manufacturer: National Semiconductor; CompType: MiscPower; PackageTopMarking: ZXTT*5022
footprint MUB10A_N (TSSOP, 10-Leads, Body 3x3mm, Pitch 0.5mm, IPC Medium Density)
footprint MUB10A_L (TSSOP, 10-Leads, Body 3x3mm, Pitch 0.5mm, IPC High Density)
footprint MUB10A_M (TSSOP, 10-Leads, Body 3x3mm, Pitch 0.5mm, IPC Low Density)
pins: 1 VIN (power), 2 FB (in), 3 COMP, 4 VCC (power), 5 OUT (out), 6 GND (power), 7 ULVO (in), 8 CS (in), 9 RT/SYNC (in), 10 SS (in)

## LM5085MMX/NOPB
designator U?
75V Constant On-Time PFET Buck Switching Controller, 8-pin MSOP, Pb-Free; PartNumber: LM5085MMX/NOPB; Manufacturer: National Semiconductor; PackageTopMarking: ZXTT*SSTB; PowerWise: Y; CompType: Switcher
footprint MUA08A_N (TSOP, 8-Leads, Body 3x3mm, Pitch 0.65mm, IPC Medium Density)
footprint MUA08A_L (TSOP, 8-Leads, Body 3x3mm, Pitch 0.65mm, IPC High Density)
footprint MUA08A_M (TSOP, 8-Leads, Body 3x3mm, Pitch 0.65mm, IPC Low Density)
pins: 1 ADJ, 2 RT, 3 FB, 4 GND (power), 5 ISEN, 6 PGATE, 7 VCC (power), 8 VIN

## LM5085MYX/NOPB
designator U?
75V Constant On-Time PFET Buck Switching Controller, 8-pin eMSOP, Pb-Free; PartNumber: LM5085MYX/NOPB; Manufacturer: National Semiconductor; PackageTopMarking: ZXTT*SSSB; PowerWise: Y; CompType: Switcher
footprint MUY08A_N (TSOP, 8-Leads, Body 3x3mm, Pitch 0.65mm, Exposed Pad, IPC Medium Density)
footprint MUY08A_L (TSOP, 8-Leads, Body 3x3mm, Pitch 0.65mm, Exposed Pad, IPC High Density)
footprint MUY08A_M (TSOP, 8-Leads, Body 3x3mm, Pitch 0.65mm, Exposed Pad, IPC Low Density)
pins: 1 ADJ, 2 RT, 3 FB, 4 GND (power), 5 ISEN, 6 PGATE, 7 VCC (power), 8 VIN, 9 EP

## LM5100AM/NOPB
designator U?
3A High Voltage High-Side and Low-Side Gate Driver, 8-pin Narrow SOIC, Pb-Free; PartNumber: LM5100AM/NOPB; Manufacturer: National Semiconductor; PackageTopMarking: NSZXTT*L5100*AM; PowerWise: N; CompType: MiscPower
footprint M08A_N (SOIC, 8-Leads, Body 4.9x3.9mm, Pitch 1.27mm, IPC Medium Density)
footprint M08A_L (SOIC, 8-Leads, Body 4.9x3.9mm, Pitch 1.27mm, IPC High Density)
footprint M08A_M (SOIC, 8-Leads, Body 4.9x3.9mm, Pitch 1.27mm, IPC Low Density)
pins: 1 VDD (power), 2 HB (power), 3 HO (out), 4 HS (power), 5 HI (in), 6 LI (in), 7 VSS (power), 8 LO (out)

## LM5100AMR/NOPB
designator U?
3A High Voltage High-Side and Low-Side Gate Driver, 8-pin PSOP, Pb-Free; PartNumber: LM5100AMR/NOPB; Manufacturer: National Semiconductor; PackageTopMarking: NSXYTT*L5100*AMR; PowerWise: N; CompType: MiscPower
footprint MRA08A_N (SOIC, 8-Leads, Body 4.9x3.9mm, Pitch 1.27mm, Exposed Pad, IPC Medium Density)
footprint MRA08A_L (SOIC, 8-Leads, Body 4.9x3.9mm, Pitch 1.27mm, Exposed Pad, IPC High Density)
footprint MRA08A_M (SOIC, 8-Leads, Body 4.9x3.9mm, Pitch 1.27mm, Exposed Pad, IPC Low Density)
pins: 1 VDD (power), 2 HB (power), 3 HO (out), 4 HS (power), 5 HI (in), 6 LI (in), 7 VSS (power), 8 LO (out), 9 EP (power)

## LM5116WG
designator U?
Wide Range Synchronous Buck Controller; Vendor: National Semiconductor; CompType: Switcher
footprint WG20A
pins: 1 VIN, 2 UVLO, 3 RT/SYNC, 4 EN, 5 RAMP, 6 AGND, 7 SS, 8 FB, 9 COMP, 10 VOUT, 11 DEMB, 12 CS, 13 CSG, 14 PGND, 15 LO, 16 VCC, 17 VCCX, 18 HB, 19 HO, 20 SW

## LM5117PMH/NOPB
designator U1  Supplier Part Number: LM5117PMH/NOPB-ND
Wide Voltage Range Buck Controller, 20-pin TSSOP-EP, Pb-Free; Manufacturer: National Semiconductor; PackageTopMarking: NSUZXYTT*LM5118*MH; PowerWise: Y; CompType: Switcher; Isolated: No; Buck: Yes; Voltage - Supply: 5.5 V ~ 65 V; Duty Cycle: 95%; Frequency - Max: 530kHz; Number of Outputs: 1; PWM Type: Current Mode
footprint MXA20A_N (TSOP, 20-Leads, Body 6.5x4.4mm, Pitch 0.65mm, Exposed Pad, IPC Medium Density)
footprint MXA20A_L (TSOP, 20-Leads, Body 6.5x4.4mm, Pitch 0.65mm, Exposed Pad, IPC High Density)
footprint MXA20A_M (TSOP, 20-Leads, Body 6.5x4.4mm, Pitch 0.65mm, Exposed Pad, IPC Low Density)
pins: 1 UVLO, 2 DEMB, 3 RES, 4 SS, 5 RT, 6 AGND (power), 7 VCCDIS, 8 FB, 9 COMP, 10 CM, 11 RAMP, 12 CS, 13 CSG, 14 PGND (power), 15 LO, 16 VCC (power), 17 SW (power), 18 HO, 19 HB, 20 VIN (power), 21 EP (power)

## LM5119PSQE/NOPB
designator U?
IC CTRL SYNC BUCK DUAL 32-LLP; PartNumber: LM5119PSQE/NOPB; Manufacturer: National Semiconductor; PowerWise: Y; CompType: Switcher
footprint SQA32A (QFN, 32-Leads, Body 5x5mm, Pitch 0.5mm, NSC Recommended)
pins: 1 VCC1 (power) "Current limit setting input for channel 2", 2 LO1 "Output clockCLKOUT is shifted 90 degrees from SYNC input", 3 PGND1 (power) "Power good signal for channel 2 under-voltage and over-voltage", 4 CSG1 "Error amplifier input for channel 2", 5 CS1 "Error amplifier ground sense for channel 2", 6 RAMP1 "Supply for low-side gate drivers", 7 SS1 "Channel 1 low-side gate drive for external MOSFET", 8 VCCDIS "Channel 1 high-side gate drive for external MOSFET", 9 FB1 "Channel 2 low-side gate drive for external MOSFET", 10 COMP1 "Chip supply voltage, input to the VDD and VDR regulators(3.3V to 18.5V)", 11 EN2 "Boost voltage for channel 1 high-side driver", 12 AGND (power) "Power good signal for channel 1 under-voltage and over-voltage", 13 RT "Power ground for channel 1 low-side drivers", 14 RES "Switch node sense for channel 1", 15 COMP2 "Error amplifier input for channel 1", 16 FB2 "Error amplifier output for channel 1", 17 DEMB "Current limit setting input for channel 1", 18 SS2 "Error amplifier ground sense for channel 1", 19 RAMP2 "Supply for control circuitry", 20 CS2 "Channel 1 track input", 21 CSG2 "Channel 1 enable input. Used to set the emulated current slope for channel 1", 22 PGND2 (power) "Frequency set / synchronization input for internal PLL", 23 LO2 "Channel 1 soft-start", 24 VCC2 (power) "Error amplifier output for channel 2", 25 SW2 "Channel 2 track input", 26 HO2 "Channel 2 soft-start", 27 HB2 "Channel 2 enable input. Used to set the emulated current slope for channel 2", 28 UVLO "Power ground for channel 2 low-side drivers", 29 VIN (power) "Switch node sense for channel 2", 30 HB1 "Channel 2 high-side gate drive for external MOSFET", 31 HO1 "Boost voltage for channel 2 high-side driver", 32 SW1 "Local signal ground", 33 DAP (power) "Exposed die attach pad. Connect the DAP directly to SGND"

## LM25116
designator U?
Wide Range Synchronous Buck Controller; Vendor: National Semiconductor; CompType: Switcher
footprint MXA20A_N (TSOP, 20-Leads, Body 6.5x4.4mm, Pitch 0.65mm, Exposed Pad, IPC Medium Density)
pins: 1 VIN, 2 UVLO, 3 RT/SYNC, 4 EN, 5 RAMP, 6 AGND, 7 SS, 8 FB, 9 COMP, 10 VOUT, 11 DEMB, 12 CS, 13 CSG, 14 PGND, 15 LO, 16 VCC, 17 VCCX, 18 HB, 19 HO, 20 SW, 21 EP

## LM25117QPMH/NOPB
designator U1
Wide Voltage Range Buck Controller, 20-pin TSSOP-EP, Pb-Free; Manufacturer: National Semiconductor; PowerWise: Y; Number of Outputs: 1
footprint MXA20A_N (TSOP, 20-Leads, Body 6.5x4.4mm, Pitch 0.65mm, Exposed Pad, IPC Medium Density)
footprint MXA20A_L (TSOP, 20-Leads, Body 6.5x4.4mm, Pitch 0.65mm, Exposed Pad, IPC High Density)
footprint MXA20A_M (TSOP, 20-Leads, Body 6.5x4.4mm, Pitch 0.65mm, Exposed Pad, IPC Low Density)
pins: 1 UVLO, 2 DEMB, 3 RES, 4 SS, 5 RT, 6 AGND (power), 7 VCCDIS, 8 FB, 9 COMP, 10 CM, 11 RAMP, 12 CS, 13 CSG, 14 PGND (power), 15 LO, 16 VCC (power), 17 SW (power), 18 HO, 19 HB, 20 VIN (power), 21 EP (power)

## LM25117QPSQ/NOPB
designator U1
Wide Voltage Range Buck Controller, 24-pin LLP, Pb-Free; Manufacturer: National Semiconductor; PowerWise: Y
footprint SQA24A (QFN, 24-Leads, Body 4x4mm, Pitch 0.5mm, NSC Recommended)
footprint SQA24A-1 (QFN, 24-Leads, Body 4x4mm, Pitch 0.5mm, 4 x 20mil vias)
pins: 1 DEMB, 2 RES, 3 SS, 4 RT, 5 AGND (power), 6 NC, 7 VCCDIS, 8 FB, 9 COMP, 10 CM, 11 RAMP, 12 CS, 13 CSG, 14 PGND (power), 15 LO, 16 VCC (power), 17 NC, 18 SW (power), 19 HO, 20 HB, 21 NC, 22 VIN (power), 23 NC, 24 UVLO, 25 EP (power)

## LM31919C_µSMD12
designator U?, comment LM34919CQTL/NOPB
IC BUCK ADJ 40V 0.6A  COT, 12PIN µSMD, 2mm X 2mm; Manufacturer: Texas Instruments; SymbolCreator: bkinsc; U/M: EA
footprint TLA12J1A_nSMD (12 Bump µSMD,  non-Solder Mask Defined, 2 x 2mm)
footprint TLA12J1A_SMD (12 Bump µSMD,  Solder Mask Defined, 2 x 2mm)
footprint TLA12J1A_sSMD (12 Bump µSMD,  Solder Mask Defined, 2 x 2mm)
pins: A1 RON, A2 RTN, A3 FB, B1 SGND, B2 PGD, B3 SS, C1 ISEN, C2 EN, C3 VCC, D1 VIN, D2 SW, D3 BST

## LM34937QPMH/NOPB
designator U1
Wide Voltage Range Buck Controller, 20-pin TSSOP-EP, Pb-Free; Manufacturer: National Semiconductor; PowerWise: Y; Number of Outputs: 1
footprint MXA20A_N (TSOP, 20-Leads, Body 6.5x4.4mm, Pitch 0.65mm, Exposed Pad, IPC Medium Density)
footprint MXA20A_L (TSOP, 20-Leads, Body 6.5x4.4mm, Pitch 0.65mm, Exposed Pad, IPC High Density)
footprint MXA20A_M (TSOP, 20-Leads, Body 6.5x4.4mm, Pitch 0.65mm, Exposed Pad, IPC Low Density)
pins: 1 UVLO, 2 DEMB, 3 RES, 4 SS, 5 RT, 6 AGND (power), 7 VCCDIS, 8 FB, 9 COMP, 10 CM, 11 RAMP, 12 CS, 13 CSG, 14 PGND (power), 15 LO, 16 VCC (power), 17 SW (power), 18 HO, 19 HB, 20 VIN (power), 21 EP (power)

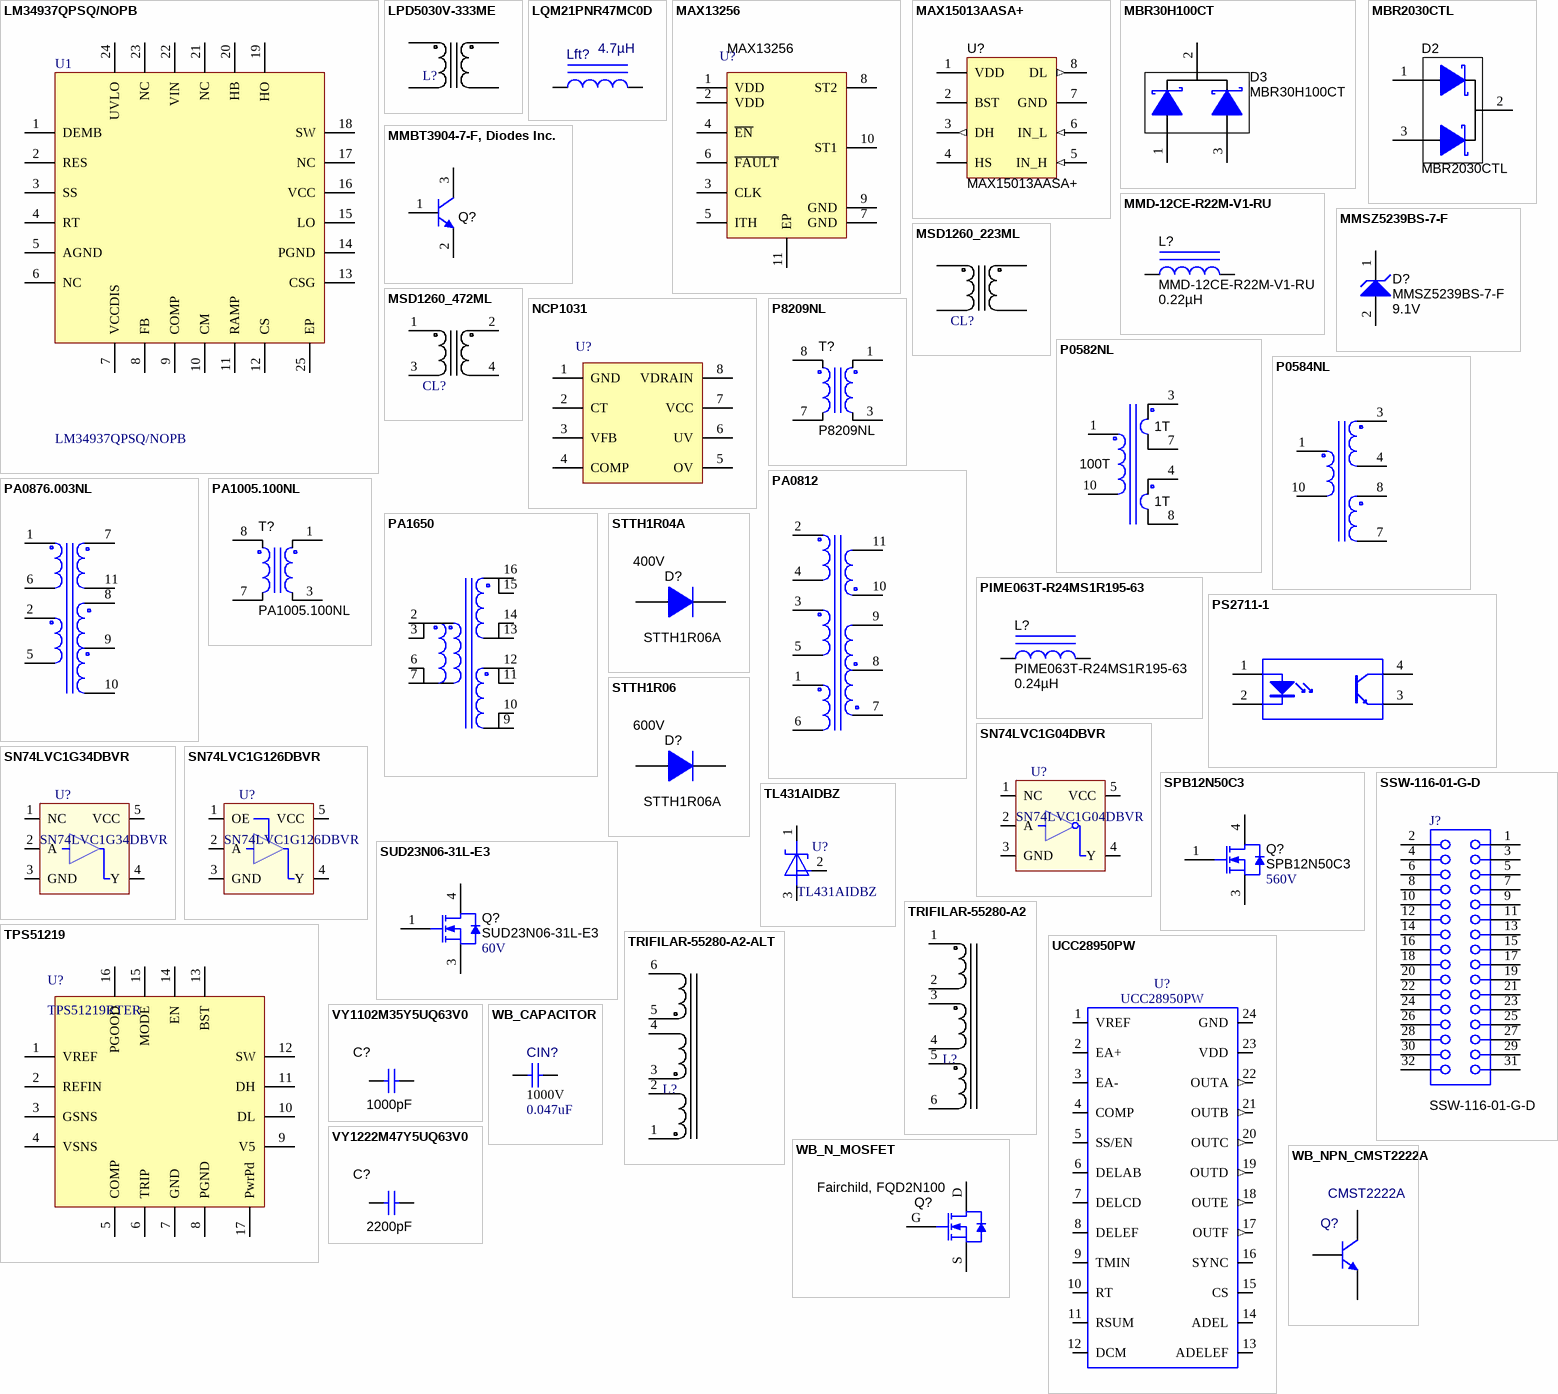
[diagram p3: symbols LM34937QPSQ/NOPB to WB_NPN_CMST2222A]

## LM34937QPSQ/NOPB
designator U1
Wide Voltage Range Buck Controller, 24-pin LLP, Pb-Free; Manufacturer: National Semiconductor; PowerWise: Y
footprint SQA24A (QFN, 24-Leads, Body 4x4mm, Pitch 0.5mm, NSC Recommended)
footprint SQA24A-1 (QFN, 24-Leads, Body 4x4mm, Pitch 0.5mm, 4 x 20mil vias)
pins: 1 DEMB, 2 RES, 3 SS, 4 RT, 5 AGND (power), 6 NC, 7 VCCDIS, 8 FB, 9 COMP, 10 CM, 11 RAMP, 12 CS, 13 CSG, 14 PGND (power), 15 LO, 16 VCC (power), 17 NC, 18 SW (power), 19 HO, 20 HB, 21 NC, 22 VIN (power), 23 NC, 24 UVLO, 25 EP (power)

## LPD5030V-333ME
designator L?  (value not drawn)
Coupled Inductor; Manufacturer: CoilCraft; Series L (uH): 33; Series DCR: 0.815; Series Isat (A): 0.53
pins: 1, 2 3, 3 2, 4

## LQM21PNR47MC0D
designator Lft?, comment ValueDisplayed: 4.7µH  (hidden comment: BRC2016T4R7M)
Inductor, Multilayer, Ferrite, 470nH, 0.66A, 0.35 ohm, SMD; Manufacturer: Taiyo Yuden; Current Rating: 610mA; Current - Saturation: 660mA; Tolerance_%: ±20%; Shielding: Unshielded; DCR_Ohm: 351 mOhm Max; Frequency - Self Resonant: 78MHz; Frequency - Test: 100kHz
footprint 0805L
footprint 1210 (1210 from SM-752 data)
footprint 0806
pins: 1, 2

## MAX13256
designator U?  PartNumber: MAX13256
36V H-Bridge Transformer Driver for Isolated Supplies; Manufacturer: Maxim Integrated; Input Type: Non-Inverting; Number of Outputs: 2; Current - Output / Channel: 300mA; Current - Peak Output: Adjustable/Programmable; Voltage - Supply: 8 V ~ 36 V
footprint LDA10A (PSON, 10-Leads, Body 3x3mm, Pitch 0.5mm, NSC Recommended)
pins: 1 VDD (power), 2 VDD (power), 3 CLK (power), 4 ~{EN} (power), 5 ITH (power), 6 ~{FAULT} (power), 7 GND (power), 8 ST2 (power), 9 GND (power), 10 ST1 (power), 11 EP (power)

## MAX15013AASA+
designator U?
2A 175V High-Side and Low-Side Gate Driver, 8-pin Narrow SOIC, Pb-Free; Manufacturer: Maxim Integrated Products; PowerWise: N; CompType: MiscPower
footprint M08A_N (SOIC, 8-Leads, Body 4.9x3.9mm, Pitch 1.27mm, IPC Medium Density)
footprint M08A_L (SOIC, 8-Leads, Body 4.9x3.9mm, Pitch 1.27mm, IPC High Density)
footprint M08A_M (SOIC, 8-Leads, Body 4.9x3.9mm, Pitch 1.27mm, IPC Low Density)
pins: 1 VDD (power), 2 BST (power), 3 DH (out), 4 HS (power), 5 IN_H (in), 6 IN_L (in), 7 GND (power), 8 DL (out)

## MBR30H100CT
designator D3
Diode, Schottky, 100V, 30A, TO-220; Manufacturer: ON Semiconductor; Value: 0.8V; U/M: EA; Vf_V: 0.8; Io_A: 20; Vr_V: 100; TJmax_C: 150; RJC_CperW: 2
signal-integrity model Diode
simulation model mbrb20100ct
footprint TO-220AB (Footprint not found)
pins: 1 A, 2 K, 3 A

## MBR2030CTL
designator D2
Diode, Schottky, 30V, 20A, TO-220; Manufacturer: On Semiconductor; Value: 0.52V; U/M: EA; Vf_V: 0.52; Io_A: 15; Vr_V: 30; TJmax_C: 150; RJC_CperW: 3
signal-integrity model Diode
simulation model DI_MBRB1530CT
footprint TO-220AB (Footprint not found)
pins: 1 A, 2 K, 3 A

## MMBT3904-7-F, Diodes Inc.
designator Q?, comment MMBT3904-7-F  (value not drawn)
Transistor, NPN, 40V, 0.2A, SOT-23; Manufacturer: Diodes Inc.; Alternate Manufacturer: None; CompType: BJT; U/M: EA; PNP: 0; NPN: 1; Vceo_V: 40; Vcesat1_V: 0.2; Value: 0.2V; HfeMax: 400
footprint SOT-23
footprint SOT-23M
footprint SOT-23L
simulation model DI_MMBT3904
pins: 1 B, 2 E, 3 C

## MMD-12CE-R22M-V1-RU
designator L?  ValueDisplayed: 0.22µH
Inductor, Shielded Composite Powder, 0.22uH, 38.5A, 0.0012 ohm, SMD; Manufacturer: Mag.Layers; Ind_H: 47.0E-6; Imax_A: 38.5; Irms: 38.5A @ 40C rise; Isat: 65A @ 20% inductance drop; DCR_ohm: 0.0012; Material: Powdered Iron; U/M: EA
signal-integrity model Inductor
simulation model Inductor
footprint MMD-12CE-SERIES-V1-RU (Mag.Layers land pattern)
pins: 1, 2

## MMSZ5239BS-7-F
designator D?  value 9.1V
Diode, Zener, 9.1V, 200mW, SOD-323; Manufacturer: Diodes Inc.; U/M: EA; Power_W: 0.2; Vz_V: 9.1; Value1: 0.2W; RJA_CperW: 350
signal-integrity model Diode
footprint sod-323
pins: 1 K, 2 A

## MSD1260_223ML
designator CL?  (value not drawn)
Coupled Inductor; Manufacturer: CoilCraft; PartNumber: MSD1260-223ML; Series L (uH): 22; Series DCR: 0.058; Series Isat (A): 5.01; Parallel L (uH): 88; Parallel DCR: 0.232; Parallel Isat (A): 2.51
footprint MSD1260-Parallel
footprint MSD1260-Series
footprint MSD1260-Dual
pins: 1, 2 3, 3 2, 4

## MSD1260_472ML
designator CL?  (value not drawn)
Coupled Inductor; Manufacturer: CoilCraft; PartNumber: MSD1260-472ML; Series L (uH): 18.8; Series DCR: 0.072; Series Isat (A): 5.15; Parallel L (uH): 4.7; Parallel DCR: 0.018; Parallel Isat (A): 10.3
footprint MSD1260-Parallel
footprint MSD1260-Series
footprint MSD1260-Dual
pins: 1, 2 3, 3 2, 4

## NCP1031
designator U?
200V PWM Regulator with integrated FET; PartNumber: NCP1031; Manufacturer: ON Seminconductor
footprint M08A_L (SOIC, 8-Leads, Body 4.9x3.9mm, Pitch 1.27mm, IPC High Density)
pins: 1 GND, 2 CT, 3 VFB, 4 COMP (power), 5 OV, 6 UV, 7 VCC (power), 8 VDRAIN

## P0582NL
designator T?
Pulse Offline Current Sense Transformer; Manufacturer: Pulse Engineering; SymbolCreator: crossc; Primary Turns: 100; Lp: 19mH
footprint P0584 (Pulse offline gate drive transformer)
pins: 1, 3, 4, 7, 8, 10

## P0584NL
designator T?
Pulse Offline Gate Drive Transformer; Manufacturer: Pulse Engineering; SymbolCreator: crossc; LeakageL: 0.5uH; Lp: 450uH
footprint P0584 (Pulse offline gate drive transformer)
pins: 1, 3, 4, 7, 8, 10

## P8209NL
designator T?
SMT Current Sense Tranformer; Manufacturer: Pulse Engineering; CompType: Transformer; Ns1toNp: 1:125; Rp: 6 mOhm; Rs1: 6.5 Ohm; SymbolCreator: codlsc; U/M: EA
footprint P82xx
pins: 1, 3, 7, 8

## PA0812
designator T?
High Frequiency Planar Transformer; Manufacturer: Pulse Engineering; SymbolCreator: codlsc; LeakageL: 0.45uH; Lp: 194uH
footprint PA08XX (Recommended land pattern for Pulse PA08xxNL series of transformers)
pins: 1, 2, 3, 4, 5, 6, 7, 8, 9, 10, 11

## PA0876.003NL
designator T?
High Frequency Planar Transformer; Manufacturer: Pulse Engineering; SymbolCreator: codlsc; LeakageL: 0.45uH; Lp: 243uH
footprint PA0876 (Recommended land pattern for Pulse PA0876NL transformer)
pins: 1, 2, 5, 6, 7, 8, 9, 10, 11

## PA1005.100NL
designator T?
SMT Current Sense Transformer; Manufacturer: Pulse Engineering; Ns1toNp: 1:100; Rp: 0.75 mOhm; Rs1: 5.5 Ohm; SymbolCreator: codlsc; U/M: EA
footprint P82xx (Footprint not found)
pins: 1, 3, 7, 8

## PA1650
designator T?, comment PA1650NL
Pulse Phase Shifted Full Bridge Transformer; Manufacturer: Pulse Engineering; SymbolCreator: crossc; LeakageL: 10uH; Lp: 252uH
footprint PA1650 (Recommended land pattern for Pulse PA1650 transformer)
pins: 2, 3, 6, 7, 9, 10, 11, 12, 13, 14, 15, 16

## PIME063T-R24MS1R195-63
designator L?  ValueDisplayed: 0.24µH
Inductor, Shielded Composite Powder, 0.24uH, 32A, 0.00119 ohm, SMD; Manufacturer: Cyntec; Ind_H: 0.24E-6; Imax_A: 32; Irms: 35A @ 40C rise; Isat: 32A @ 30% inductance drop; Material: Powdered Iron; U/M: EA
signal-integrity model Inductor
simulation model Inductor
footprint PIME063T-R24MS1R195-63 (Cyntec land pattern)
pins: 1, 2

## PS2711-1
designator U?
Low Input Current, Hight CTR Photocoupler; Manufacturer: NEC; CompType: OPTOCOUPLER; SymbolCreator: crossc; Number of Channels: 1; Input Type: DC; Voltage - Isolation: 3750Vrms; Current Transfer Ratio (Min): 100% @ 1mA; Current Transfer Ratio (Max): 400% @ 1mA; Voltage - Output: 40V; Current - DC Forward (If): 50mA; Vce Saturation (Max): 300mV; Output Type: Transistor
footprint PS2711-1 (NEC optocoupler)
pins: 1 A, 2 K, 3 E, 4 C

## SN74LVC1G04DBVR
designator U?
IC, Single Gate Inverter; Manufacturer: Texas Instruments; Area: 16384; PCB DECAL: SOT23-5
footprint MF05A_L (SOT23, 5-Leads, Body 2.9x1.6mm, Pitch 0.95mm, Lead Span 2.8mm, IPC High Density)
footprint MF05A_M (SOT23, 5-Leads, Body 2.9x1.6mm, Pitch 0.95mm, Lead Span 2.8mm, IPC Low Density)
footprint MF05A_N (SOT23, 5-Leads, Body 2.9x1.6mm, Pitch 0.95mm, Lead Span 2.8mm, IPC Medium Density)
pins: 1 NC, 2 A, 3 GND, 4 Y, 5 VCC

## SN74LVC1G34DBVR
designator U?
IC, Single Buffer Gate; Manufacturer: Texas Instruments; Area: 16384; PCB DECAL: SOT23-5
footprint MF05A_L (SOT23, 5-Leads, Body 2.9x1.6mm, Pitch 0.95mm, Lead Span 2.8mm, IPC High Density)
footprint MF05A_M (SOT23, 5-Leads, Body 2.9x1.6mm, Pitch 0.95mm, Lead Span 2.8mm, IPC Low Density)
footprint MF05A_N (SOT23, 5-Leads, Body 2.9x1.6mm, Pitch 0.95mm, Lead Span 2.8mm, IPC Medium Density)
pins: 1 NC, 2 A, 3 GND, 4 Y, 5 VCC

## SN74LVC1G126DBVR
designator U?
IC, Single Buffer Gate with 3-State Output; Manufacturer: Texas Instruments; Area: 16384; PCB DECAL: SOT23-5
footprint MF05A_L (SOT23, 5-Leads, Body 2.9x1.6mm, Pitch 0.95mm, Lead Span 2.8mm, IPC High Density)
footprint MF05A_M (SOT23, 5-Leads, Body 2.9x1.6mm, Pitch 0.95mm, Lead Span 2.8mm, IPC Low Density)
footprint MF05A_N (SOT23, 5-Leads, Body 2.9x1.6mm, Pitch 0.95mm, Lead Span 2.8mm, IPC Medium Density)
pins: 1 OE, 2 A, 3 GND, 4 Y, 5 VCC

## SPB12N50C3
designator Q?  value 560V
MOSFET, N-CH, 560V, 11.6A, DDPAK; Manufacturer: Infineon; ChType: N; VdsMax_V: 560; Value1: 0.38 ohm; Value2: 49 nC; QgTyp_nC: 49; Vgs_V: 20; IdsMax_A: 11.6
footprint DDPAK
pins: 1 G, 3 S, 4 D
